// Mitsubishi GX Works2 project: BD4543通信   PLC: FX3U/FX3UC

PROGRAM MAIN
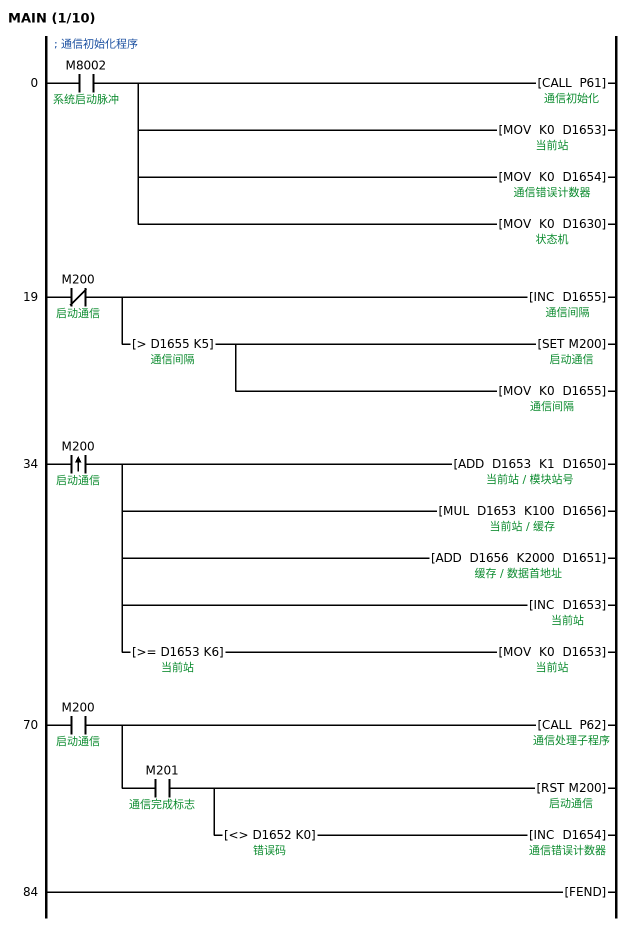
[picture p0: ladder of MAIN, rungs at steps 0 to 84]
; 通信初始化程序
; 
0     LD      M8002  ; 系统启动脉冲
      CALL    P61  ; 通信初始化
      MOV     K0 D1653  ; 当前站
      MOV     K0 D1654  ; 通信错误计数器
      MOV     K0 D1630  ; 状态机
19    LDI     M200  ; 启动通信
      INC     D1655  ; 通信间隔
      AND>    D1655 K5  ; 通信间隔
      SET     M200  ; 启动通信
      MOV     K0 D1655
34    LDP     M200  ; 启动通信
      ADD     D1653 K1 D1650  ; 模块站号
      MUL     D1653 K100 D1656  ; 缓存
      ADD     D1656 K2000 D1651  ; 数据首地址
      INC     D1653
      AND>=   D1653 K6  ; 当前站
      MOV     K0 D1653
70    LD      M200  ; 启动通信
      CALL    P62  ; 通信处理子程序
      AND     M201  ; 通信完成标志
      RST     M200  ; 启动通信
      AND<>   D1652 K0  ; 错误码
      INC     D1654
84    FEND
; 通信初始化设置子程序
; 占用资源：D1700~D1955（CRC余数表）
; 
      P61
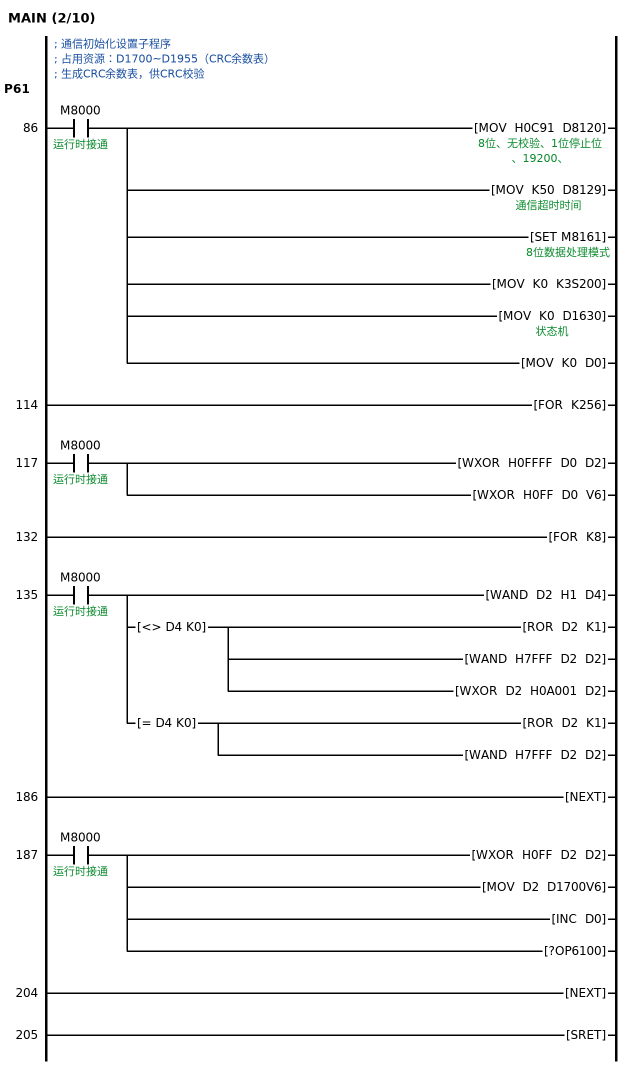
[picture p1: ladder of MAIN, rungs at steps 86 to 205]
86    LD      M8000  ; 运行时接通
      MOV     H0C91 D8120  ; 8位、无校验、1位停止位、19200、
      MOV     K50 D8129  ; 通信超时时间
      SET     M8161  ; 8位数据处理模式
      MOV     K0 K3S200
      MOV     K0 D1630
      MOV     K0 D0
; 生成CRC余数表，供CRC校验
114   FOR     K256
117   LD      M8000  ; 运行时接通
      WXOR    H0FFFF D0 D2
      WXOR    H0FF D0 V6
132   FOR     K8
135   LD      M8000  ; 运行时接通
      WAND    D2 H1 D4
      MPS
      AND<>   D4 K0
      ROR     D2 K1
      WAND    H7FFF D2 D2
      WXOR    D2 H0A001 D2
      MPP
      AND=    D4 K0
      ROR     D2 K1
      WAND    H7FFF D2 D2
186   NEXT
187   LD      M8000  ; 运行时接通
      WXOR    H0FF D2 D2
      MOV     D2 D1700V6
      INC     D0
      ?OP6100
204   NEXT
205   SRET
; BD4543通信处理子程序
; 输入参数：D1650 模块站号
; D1651 数据起始地址
; 输出参数：M201 工作状态：1完成、0忙
      P62
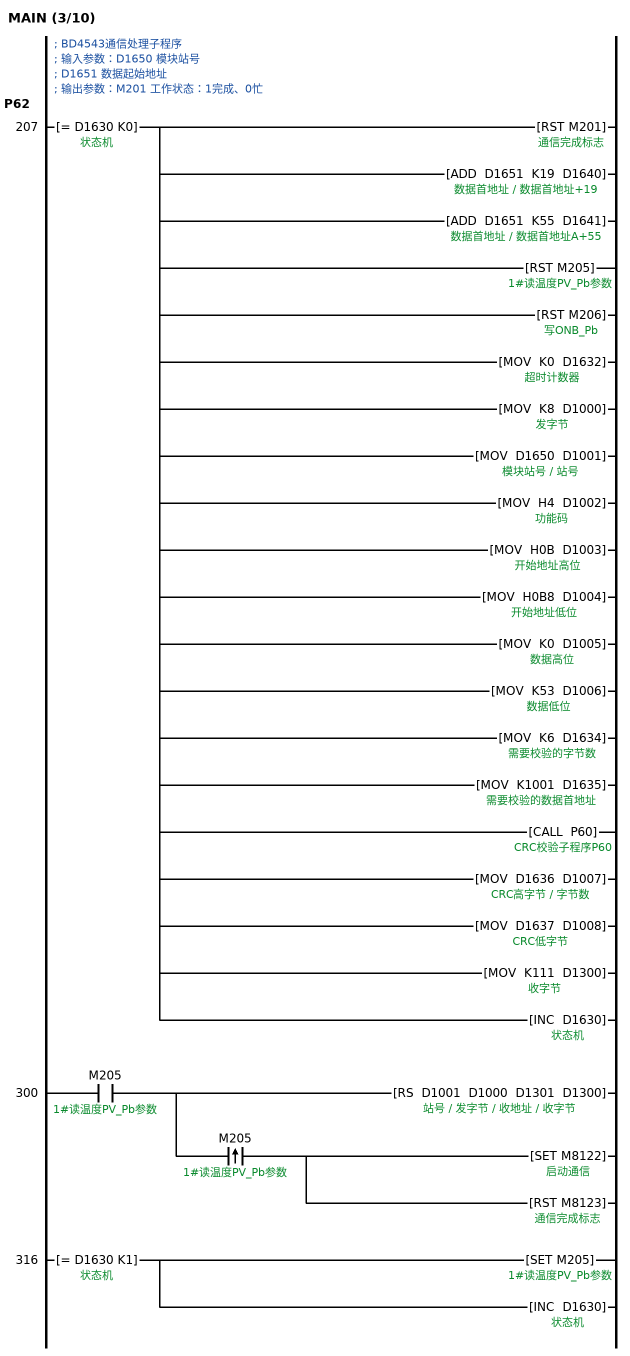
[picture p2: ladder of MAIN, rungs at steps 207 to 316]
207   LD=     D1630 K0  ; 状态机
      RST     M201  ; 通信完成标志
      ADD     D1651 K19 D1640  ; 数据首地址+19
      ADD     D1651 K55 D1641  ; 数据首地址A+55
      RST     M205  ; 1#读温度PV_Pb参数
      RST     M206  ; 写ONB_Pb
      MOV     K0 D1632  ; 超时计数器
      MOV     K8 D1000  ; 发字节
      MOV     D1650 D1001  ; 站号
      MOV     H4 D1002  ; 功能码
      MOV     H0B D1003  ; 开始地址高位
      MOV     H0B8 D1004  ; 开始地址低位
      MOV     K0 D1005  ; 数据高位
      MOV     K53 D1006  ; 数据低位
      MOV     K6 D1634  ; 需要校验的字节数
      MOV     K1001 D1635  ; 需要校验的数据首地址
      CALL    P60  ; CRC校验子程序P60
      MOV     D1636 D1007  ; CRC高字节 / 字节数
      MOV     D1637 D1008  ; CRC低字节
      MOV     K111 D1300  ; 收字节
      INC     D1630
300   LD      M205  ; 1#读温度PV_Pb参数
      RS      D1001 D1000 D1301 D1300  ; 站号 / 发字节 / 收地址 / 收字节
      ANDP    M205  ; 1#读温度PV_Pb参数
      SET     M8122  ; 启动通信
      RST     M8123  ; 通信完成标志
316   LD=     D1630 K1  ; 状态机
      SET     M205  ; 1#读温度PV_Pb参数
      INC     D1630
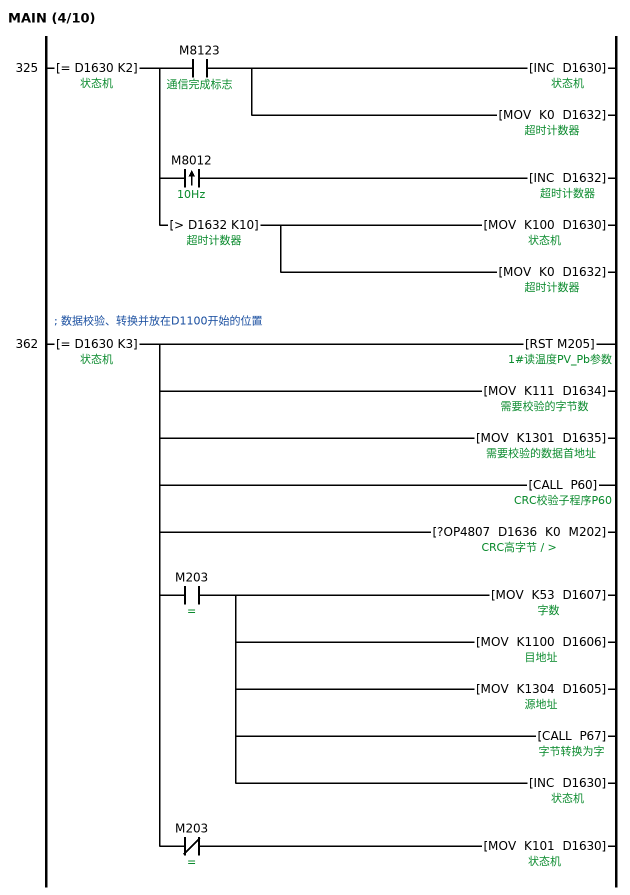
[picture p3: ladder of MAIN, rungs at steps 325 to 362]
325   LD=     D1630 K2  ; 状态机
      MPS
      AND     M8123  ; 通信完成标志
      INC     D1630
      MOV     K0 D1632
      MRD
      ANDP    M8012  ; 10Hz
      INC     D1632
      MPP
      AND>    D1632 K10  ; 超时计数器
      MOV     K100 D1630
        [note] 超时出错跳过
      MOV     K0 D1632
; 数据校验、转换并放在D1100开始的位置
362   LD=     D1630 K3  ; 状态机
      RST     M205  ; 1#读温度PV_Pb参数
      MOV     K111 D1634
      MOV     K1301 D1635
      CALL    P60
      ?OP4807 D1636 K0 M202  ; >
      MPS
      AND     M203  ; =
      MOV     K53 D1607  ; 字数
      MOV     K1100 D1606  ; 目地址
      MOV     K1304 D1605  ; 源地址
      CALL    P67  ; 字节转换为字
      INC     D1630
      MPP
      ANI     M203  ; =
      MOV     K101 D1630
        [note] CRC校验错误
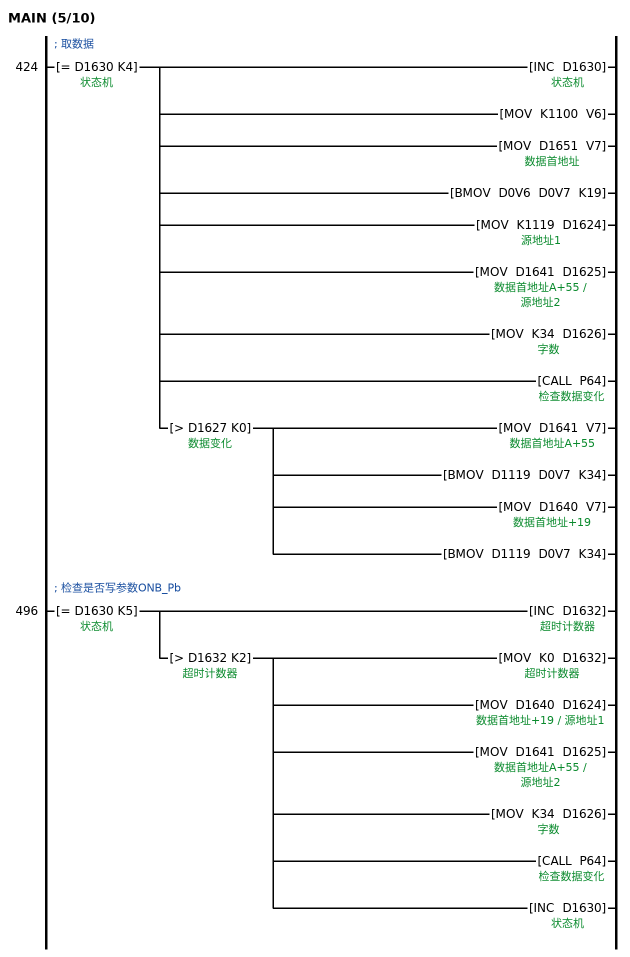
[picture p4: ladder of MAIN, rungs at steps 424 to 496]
; 取数据
424   LD=     D1630 K4  ; 状态机
      INC     D1630
      MOV     K1100 V6
      MOV     D1651 V7
      BMOV    D0V6 D0V7 K19
        [note] 温度PV RUNF ALF1 ALF2
      MOV     K1119 D1624  ; 源地址1
      MOV     D1641 D1625  ; 源地址2
      MOV     K34 D1626  ; 字数
      CALL    P64  ; 检查数据变化
      AND>    D1627 K0  ; 数据变化
      MOV     D1641 V7
      BMOV    D1119 D0V7 K34
      MOV     D1640 V7
      BMOV    D1119 D0V7 K34
; 检查是否写参数ONB_Pb
496   LD=     D1630 K5  ; 状态机
      INC     D1632
      AND>    D1632 K2  ; 超时计数器
      MOV     K0 D1632
      MOV     D1640 D1624
      MOV     D1641 D1625
      MOV     K34 D1626
      CALL    P64
      INC     D1630
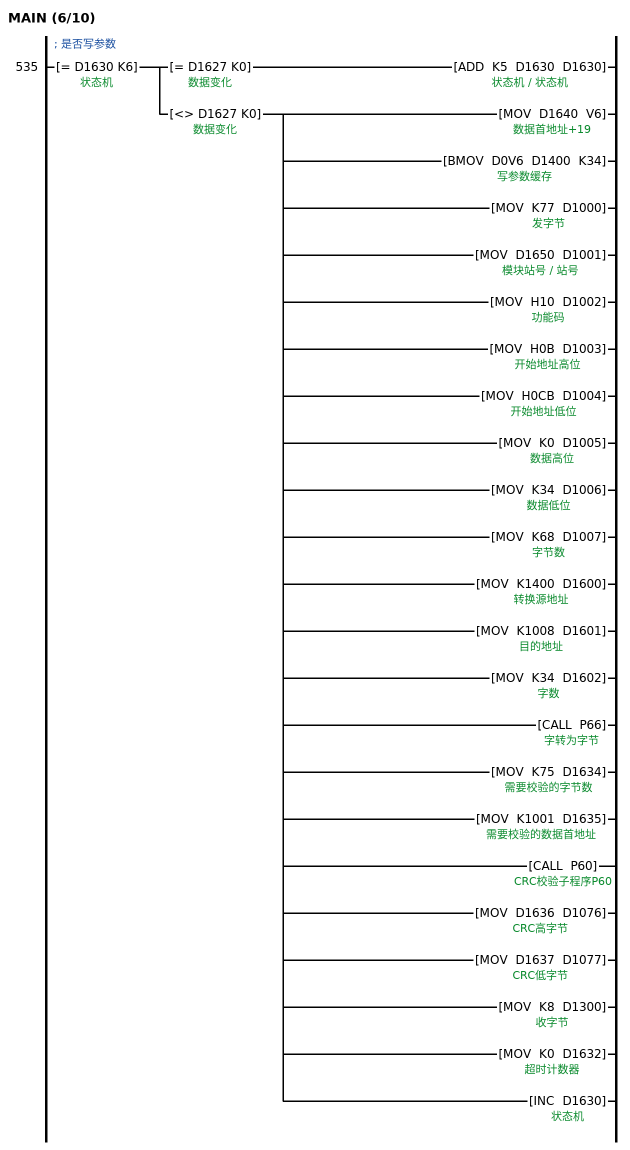
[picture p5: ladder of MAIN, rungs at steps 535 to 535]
; 是否写参数
535   LD=     D1630 K6  ; 状态机
      MPS
      AND=    D1627 K0  ; 数据变化
      ADD     K5 D1630 D1630
      MPP
      AND<>   D1627 K0  ; 数据变化
      MOV     D1640 V6
      BMOV    D0V6 D1400 K34  ; 写参数缓存
      MOV     K77 D1000
      MOV     D1650 D1001
      MOV     H10 D1002
      MOV     H0B D1003
      MOV     H0CB D1004
      MOV     K0 D1005
      MOV     K34 D1006
      MOV     K68 D1007
      MOV     K1400 D1600  ; 转换源地址
      MOV     K1008 D1601  ; 目的地址
      MOV     K34 D1602  ; 字数
      CALL    P66  ; 字转为字节
      MOV     K75 D1634
      MOV     K1001 D1635
      CALL    P60
      MOV     D1636 D1076
      MOV     D1637 D1077
      MOV     K8 D1300
      MOV     K0 D1632
      INC     D1630
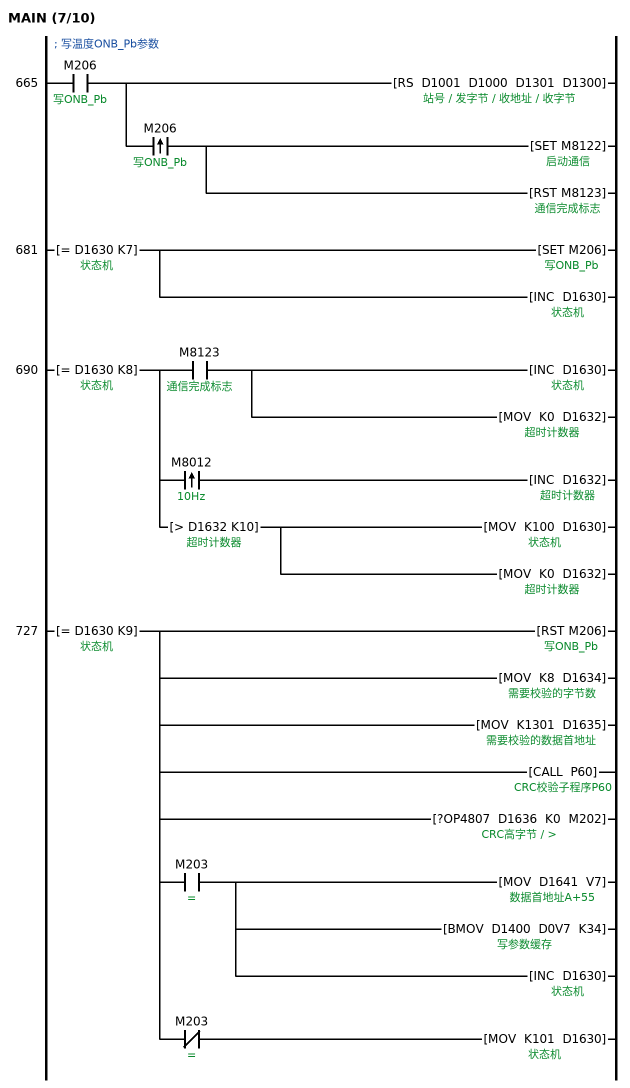
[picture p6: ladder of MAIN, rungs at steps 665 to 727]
; 写温度ONB_Pb参数
665   LD      M206  ; 写ONB_Pb
      RS      D1001 D1000 D1301 D1300  ; 站号 / 发字节 / 收地址 / 收字节
      ANDP    M206  ; 写ONB_Pb
      SET     M8122  ; 启动通信
      RST     M8123  ; 通信完成标志
681   LD=     D1630 K7  ; 状态机
      SET     M206  ; 写ONB_Pb
      INC     D1630
690   LD=     D1630 K8  ; 状态机
      MPS
      AND     M8123  ; 通信完成标志
      INC     D1630
      MOV     K0 D1632
      MRD
      ANDP    M8012  ; 10Hz
      INC     D1632
      MPP
      AND>    D1632 K10  ; 超时计数器
      MOV     K100 D1630
        [note] 超时出错跳过
      MOV     K0 D1632
727   LD=     D1630 K9  ; 状态机
      RST     M206  ; 写ONB_Pb
      MOV     K8 D1634
      MOV     K1301 D1635
      CALL    P60
      ?OP4807 D1636 K0 M202
      MPS
      AND     M203  ; =
      MOV     D1641 V7
      BMOV    D1400 D0V7 K34
      INC     D1630
      MPP
      ANI     M203  ; =
      MOV     K101 D1630
        [note] CRC校验错误
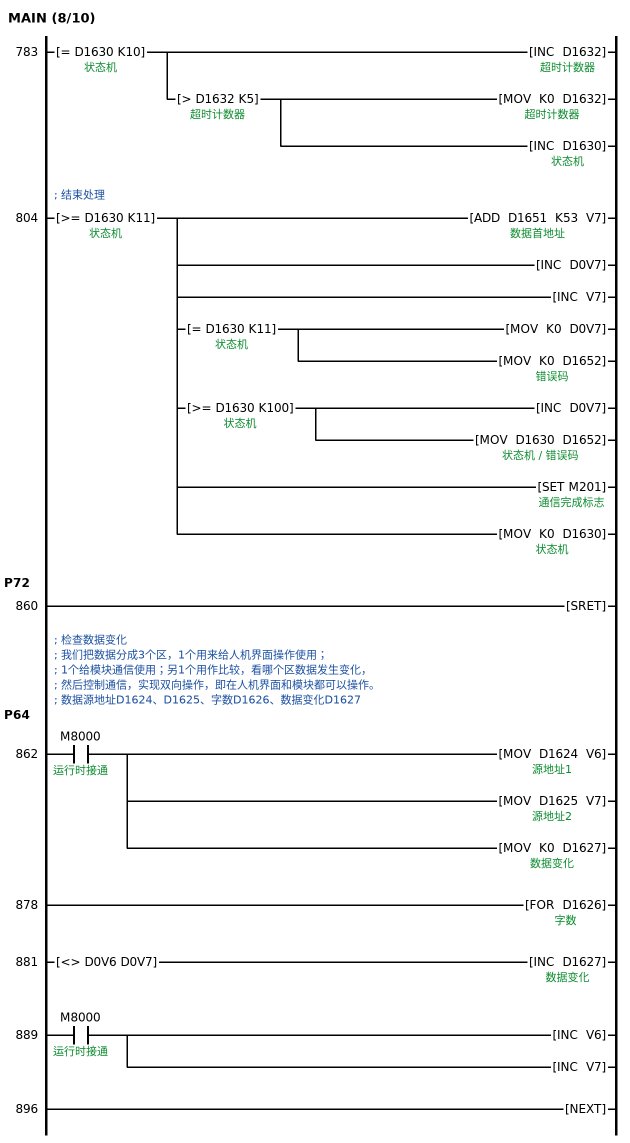
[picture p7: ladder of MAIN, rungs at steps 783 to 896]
783   LD=     D1630 K10  ; 状态机
      INC     D1632
      AND>    D1632 K5  ; 超时计数器
      MOV     K0 D1632
      INC     D1630
; 结束处理
804   LD>=    D1630 K11  ; 状态机
      ADD     D1651 K53 V7
      INC     D0V7
      INC     V7
      MPS
      AND=    D1630 K11  ; 状态机
      MOV     K0 D0V7
      MOV     K0 D1652
      MRD
      AND>=   D1630 K100  ; 状态机
      INC     D0V7
      MOV     D1630 D1652
      MPP
      SET     M201  ; 通信完成标志
      MOV     K0 D1630
      P72
860   SRET
; 检查数据变化
; 我们把数据分成3个区，1个用来给人机界面操作使用；
; 1个给模块通信使用；另1个用作比较，看哪个区数据发生变化，
; 然后控制通信，实现双向操作，即在人机界面和模块都可以操作。
; 数据源地址D1624、D1625、字数D1626、数据变化D1627
; 
      P64
862   LD      M8000  ; 运行时接通
      MOV     D1624 V6
      MOV     D1625 V7
      MOV     K0 D1627
878   FOR     D1626
881   LD<>    D0V6 D0V7
      INC     D1627
889   LD      M8000  ; 运行时接通
      INC     V6
      INC     V7
896   NEXT
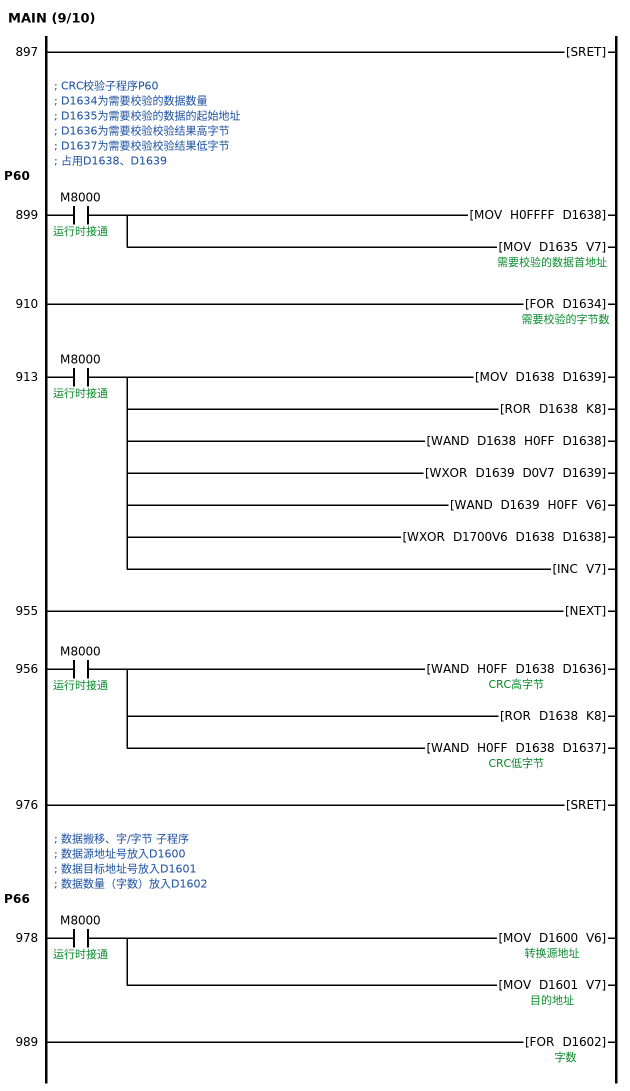
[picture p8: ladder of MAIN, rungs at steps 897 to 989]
897   SRET
; CRC校验子程序P60
; 
; D1634为需要校验的数据数量
; D1635为需要校验的数据的起始地址
; D1636为需要校验校验结果高字节
; D1637为需要校验校验结果低字节
; 占用D1638、D1639
      P60
899   LD      M8000  ; 运行时接通
      MOV     H0FFFF D1638
      MOV     D1635 V7
910   FOR     D1634
913   LD      M8000  ; 运行时接通
      MOV     D1638 D1639
      ROR     D1638 K8
      WAND    D1638 H0FF D1638
      WXOR    D1639 D0V7 D1639
      WAND    D1639 H0FF V6
      WXOR    D1700V6 D1638 D1638
      INC     V7
955   NEXT
956   LD      M8000  ; 运行时接通
      WAND    H0FF D1638 D1636
      ROR     D1638 K8
      WAND    H0FF D1638 D1637
976   SRET
; 数据搬移、字/字节 子程序
; 数据源地址号放入D1600
; 数据目标地址号放入D1601
; 数据数量（字数）放入D1602
      P66
978   LD      M8000  ; 运行时接通
      MOV     D1600 V6
      MOV     D1601 V7
989   FOR     D1602
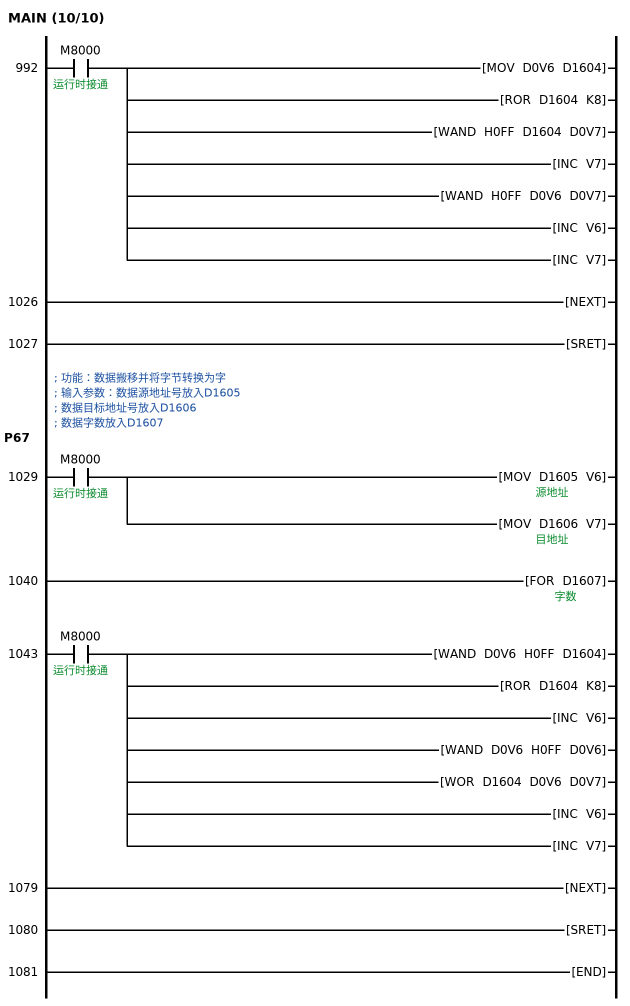
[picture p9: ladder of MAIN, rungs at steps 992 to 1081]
992   LD      M8000  ; 运行时接通
      MOV     D0V6 D1604
      ROR     D1604 K8
      WAND    H0FF D1604 D0V7
      INC     V7
      WAND    H0FF D0V6 D0V7
      INC     V6
      INC     V7
1026  NEXT
1027  SRET
; 功能：数据搬移并将字节转换为字
; 输入参数：数据源地址号放入D1605
; 数据目标地址号放入D1606
; 数据字数放入D1607
      P67
1029  LD      M8000  ; 运行时接通
      MOV     D1605 V6
      MOV     D1606 V7
1040  FOR     D1607
1043  LD      M8000  ; 运行时接通
      WAND    D0V6 H0FF D1604
      ROR     D1604 K8
      INC     V6
      WAND    D0V6 H0FF D0V6
      WOR     D1604 D0V6 D0V7
      INC     V6
      INC     V7
1079  NEXT
1080  SRET
1081  END
END_PROGRAM

// device comments not shown above
M204  ; <
D101  ; 需要校验的数据的起始地址
D102  ; CRC高字节
D103  ; CRC低字节
D110  ; 当前模块站号
D151  ; 功能码
D152  ; 起始地址高字节
D153  ; 起始地址低字节
D154  ; 数据通道数高字节
D155  ; 数据通道数低字节
D1615  ; 参数地址
D1617  ; 参数地址
D1619  ; 通道号
D1620  ; 命令码
D1621  ; 缓存
D1631  ; 时间标记
D1657  ; 缓存
D1660  ; 启动关闭整定标记
D1661  ; 通道0~7
D1662  ; 查通道
D1663  ; 要发送整定参数
D1664  ; 启动/关闭整定
D1665  ; 整定状态
T240  ; 系统启动延时
T241  ; 通信间隔时间
T242  ; 通信故障重启动时间
P65  ; 读温度及常用参数准备
P68  ; 读手动、输出、输出限位值初始化
P69  ; 写给定温度、常用参数准备
P70  ; 写手动输出、输出限位准备
P71  ; 自整定数据准备
